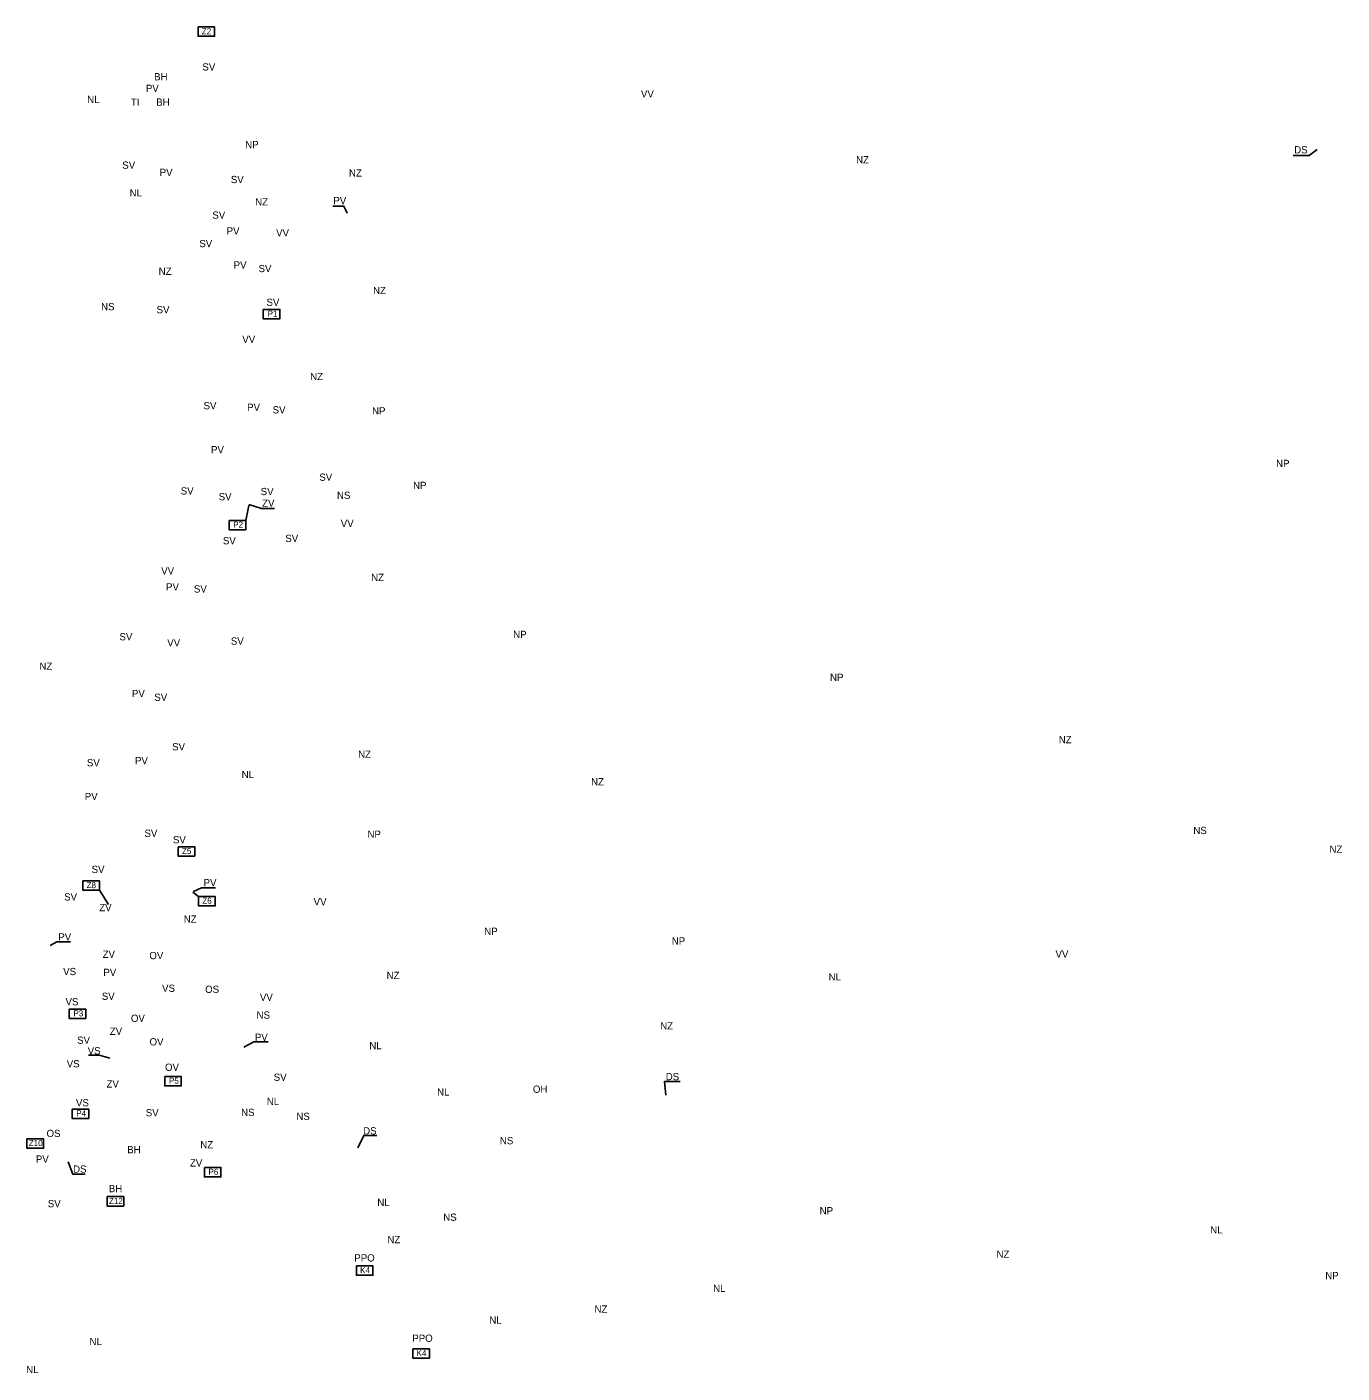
# Model space of a CAD drawing. Extents: x -546576 to -528254, y -1046225 to -1035772.
# Drawn here: x -542762 to -540580, y -1040285 to -1038051 of the extents above; entities that cross this region are included whole.
import ezdxf

# ---------------------------------------------------------------- set-up
doc = ezdxf.new("R2010")
doc.units = 0
for name, color, linetype in [('Vrstva 10', 7, 'Continuous'), ('Vrstva 11', 7, 'Continuous'), ('Vrstva 3', 7, 'Continuous'), ('Vrstva 4', 7, 'Continuous'), ('Vrstva 7', 7, 'Continuous')]:
    doc.layers.add(name, color=color, linetype=linetype)

msp = doc.modelspace()

# ---------------------------------------------------------------- linework, layer by layer
at = {"layer": 'Vrstva 10'}
for points in [[(-540661.6, -1038264.7), (-540634.6, -1038264.7), (-540621.3, -1038254.7)], [(-542254.3, -1038348.8), (-542235.9, -1038348.8), (-542230.2, -1038360.2)], [(-542689, -1039569), (-542711.8, -1039569), (-542722.9, -1039575.2)], [(-542361.3, -1039735), (-542385.1, -1039735), (-542401.8, -1039744)], [(-542659.5, -1039757.3), (-542641.6, -1039757.3), (-542624.1, -1039762.4)], [(-541678, -1039801.2), (-541704.1, -1039801.2), (-541701.7, -1039823.6)], [(-542181.3, -1039890.5), (-542203, -1039890.5), (-542212.9, -1039910.9)], [(-542664.8, -1039954.7), (-542685.3, -1039954.7), (-542693, -1039934.1)]]:
    msp.add_lwpolyline(points, dxfattribs=at)
at = {"layer": 'Vrstva 11'}
for points in [[(-542351.1, -1038850.2), (-542372.4, -1038850.2), (-542393.3, -1038843.9)], [(-542448.9, -1039479.7), (-542472.2, -1039479.7), (-542485.5, -1039485.7)]]:
    msp.add_lwpolyline(points, dxfattribs=at)
at = {"layer": 'Vrstva 3'}
for p, q in [((-542641.3, -1039483.7), (-542626.2, -1039507.2)), ((-542476.8, -1039494.1), (-542486.1, -1039486.6))]:
    msp.add_line(p, q, dxfattribs=at)
for points in [[(-542477.7, -1038051.5), (-542477.7, -1038067), (-542450.2, -1038067), (-542450.2, -1038051.5), (-542477.7, -1038051.5)], [(-542510.8, -1039411.6), (-542510.8, -1039427.1), (-542483.3, -1039427.1), (-542483.3, -1039411.6), (-542510.8, -1039411.6)], [(-542668.8, -1039468.1), (-542668.8, -1039483.7), (-542641.3, -1039483.7), (-542641.3, -1039468.1), (-542668.8, -1039468.1)], [(-542476.8, -1039494.1), (-542476.8, -1039509.6), (-542449.3, -1039509.6), (-542449.3, -1039494.1), (-542476.8, -1039494.1)], [(-542761.5, -1039896.1), (-542761.5, -1039911.6), (-542734, -1039911.6), (-542734, -1039896.1), (-542761.5, -1039896.1)], [(-542628.4, -1039992), (-542628.4, -1040007.5), (-542600.9, -1040007.5), (-542600.9, -1039992), (-542628.4, -1039992)]]:
    msp.add_lwpolyline(points, dxfattribs=at)
at = {"layer": 'Vrstva 4'}
msp.add_line((-542398.7, -1038870.1), (-542393.6, -1038845.3), dxfattribs=at)
for points in [[(-542369.5, -1038520), (-542369.5, -1038535.5), (-542342, -1038535.5), (-542342, -1038520), (-542369.5, -1038520)], [(-542426.2, -1038870.1), (-542426.2, -1038885.6), (-542398.7, -1038885.6), (-542398.7, -1038870.1), (-542426.2, -1038870.1)], [(-542691.4, -1039680.8), (-542691.4, -1039696.3), (-542663.9, -1039696.3), (-542663.9, -1039680.8), (-542691.4, -1039680.8)], [(-542533, -1039792.7), (-542533, -1039808.3), (-542505.5, -1039808.3), (-542505.5, -1039792.7), (-542533, -1039792.7)], [(-542686.5, -1039846.7), (-542686.5, -1039862.2), (-542659, -1039862.2), (-542659, -1039846.7), (-542686.5, -1039846.7)], [(-542467.1, -1039943.6), (-542467.1, -1039959.2), (-542439.7, -1039959.2), (-542439.7, -1039943.6), (-542467.1, -1039943.6)]]:
    msp.add_lwpolyline(points, dxfattribs=at)
at = {"layer": 'Vrstva 7'}
for points in [[(-542215.1, -1040106.9), (-542215.1, -1040122.4), (-542187.6, -1040122.4), (-542187.6, -1040106.9), (-542215.1, -1040106.9)], [(-542121.4, -1040244.3), (-542121.4, -1040259.9), (-542094, -1040259.9), (-542094, -1040244.3), (-542121.4, -1040244.3)]]:
    msp.add_lwpolyline(points, dxfattribs=at)

# ---------------------------------------------------------------- texts
at = {"layer": 'Vrstva 10'}
for s, p in [('BH', (-542550.6, -1038140.1)), ('SV', (-542470.5, -1038123.8)), ('PV', (-542564.2, -1038159.4)), ('NL', (-542661.6, -1038177.7)), ('NL', (-542661.6, -1038177.7)), ('TI', (-542589.1, -1038182.3)), ('BH', (-542547.1, -1038182.2)), ('VV', (-541743.1, -1038168.5)), ('NP', (-542399.5, -1038252.7)), ('DS', (-540659.7, -1038261.3)), ('SV', (-542603.4, -1038286.8)), ('PV', (-542541.4, -1038298.7)), ('NZ', (-541386.3, -1038277.8)), ('SV', (-542423.3, -1038310.6)), ('NZ', (-542227.4, -1038299.8)), ('NL', (-542591.2, -1038332.8)), ('NZ', (-542383, -1038347.7)), ('PV', (-542253.3, -1038345.6)), ('SV', (-542454, -1038369.7)), ('PV', (-542430.3, -1038395.8)), ('VV', (-542348.2, -1038399.1)), ('SV', (-542475.6, -1038416.9)), ('PV', (-542418.7, -1038452.4)), ('NZ', (-542543, -1038462.8)), ('SV', (-542377.4, -1038458.3)), ('NZ', (-542187.4, -1038494.7)), ('NS', (-542638.6, -1038521.5)), ('SV', (-542546.5, -1038526.6)), ('VV', (-542404.3, -1038575.7)), ('NZ', (-542291.8, -1038637.4)), ('SV', (-542468.6, -1038685.8)), ('PV', (-542396.3, -1038688.5)), ('SV', (-542354, -1038692.7)), ('NP', (-542189.1, -1038694.4)), ('PV', (-542456.2, -1038758.8)), ('NP', (-540689.7, -1038781.6)), ('SV', (-542276.6, -1038804.4)), ('SV', (-542506.4, -1038827.2)), ('SV', (-542373.8, -1038828.2)), ('NS', (-542247.3, -1038834.5)), ('NP', (-542121.1, -1038818)), ('SV', (-542443.5, -1038836.8)), ('VV', (-542241, -1038881.1)), ('SV', (-542436.5, -1038909.8)), ('SV', (-542333, -1038906)), ('VV', (-542538.8, -1038959.9)), ('PV', (-542530.8, -1038986.4)), ('SV', (-542484.6, -1038989.8)), ('NZ', (-542190.6, -1038970.7)), ('SV', (-542608, -1039069.1)), ('VV', (-542528.8, -1039079.2)), ('SV', (-542423.3, -1039076.3)), ('NP', (-541955, -1039065.3)), ('NZ', (-542740.8, -1039118)), ('NP', (-541429.5, -1039136.3)), ('PV', (-542587.4, -1039163.3)), ('SV', (-542550.3, -1039169.5)), ('SV', (-542520.7, -1039251.7)), ('NZ', (-541050.1, -1039239.7)), ('SV', (-542662.1, -1039278.1)), ('PV', (-542582.3, -1039274.6)), ('NZ', (-542212.2, -1039263.9)), ('NL', (-542405.3, -1039297.7)), ('NZ', (-541825.8, -1039309.7)), ('PV', (-542665.6, -1039334.1)), ('NS', (-540826.9, -1039390.5)), ('SV', (-542566.6, -1039395.2)), ('NP', (-542196.7, -1039396.7)), ('NZ', (-540601.1, -1039421.6)), ('SV', (-542654.3, -1039455.1)), ('SV', (-542699.8, -1039500.7)), ('VV', (-542286, -1039508.7)), ('NZ', (-542501.4, -1039537.5)), ('PV', (-542709.4, -1039567)), ('NP', (-542003.1, -1039557.8)), ('NP', (-541692, -1039573.8)), ('ZV', (-542636, -1039595.9)), ('OV', (-542558.4, -1039598)), ('VV', (-541055.5, -1039595.6)), ('VS', (-542701.4, -1039624.5)), ('PV', (-542634.8, -1039625.9)), ('NZ', (-542165, -1039630.9)), ('NL', (-541431.9, -1039633.4)), ('VS', (-542537.4, -1039652.2)), ('OS', (-542466, -1039654)), ('SV', (-542637.4, -1039665.5)), ('VV', (-542375.1, -1039667.3)), ('OV', (-542589.1, -1039702.1)), ('NS', (-542380.7, -1039696.7)), ('ZV', (-542624.1, -1039723.6)), ('NZ', (-541711.2, -1039714.6)), ('SV', (-542678.3, -1039738.4)), ('OV', (-542558.2, -1039741.1)), ('PV', (-542383.5, -1039733.5)), ('NL', (-542193.6, -1039747.5)), ('VS', (-542660.7, -1039756)), ('VS', (-542695.5, -1039777.6)), ('ZV', (-542629.5, -1039811)), ('ZV', (-542629.5, -1039811)), ('SV', (-542352.2, -1039799.9)), ('DS', (-541702, -1039798.9)), ('NL', (-542363.7, -1039839.9)), ('NL', (-542081.2, -1039824.3)), ('OH', (-541922.3, -1039819.7)), ('SV', (-542564.4, -1039858.7)), ('NS', (-542406.3, -1039858.2)), ('NS', (-542314.6, -1039864.8)), ('DS', (-542203.9, -1039888.8)), ('NS', (-541977.1, -1039905.1)), ('BH', (-542595.2, -1039920)), ('NZ', (-542474, -1039911.8)), ('PV', (-542746.7, -1039935.7)), ('DS', (-542685, -1039952.2)), ('SV', (-542726.9, -1040009.6)), ('SV', (-542726.9, -1040009.6)), ('NL', (-542180.3, -1040007.6)), ('NS', (-542071, -1040032)), ('NP', (-541446.7, -1040021.3)), ('NL', (-540798.9, -1040053)), ('NZ', (-542163.6, -1040069.2)), ('NZ', (-541153.4, -1040093.4)), ('NP', (-540608.1, -1040128.9)), ('NL', (-541623.4, -1040150)), ('NZ', (-541820.1, -1040184.5)), ('NL', (-541994.5, -1040202.8)), ('NL', (-542657.7, -1040238.3)), ('NL', (-542657.7, -1040238.3)), ('NL', (-542762.8, -1040284.7))]:
    msp.add_text(s, height=12, dxfattribs=at).set_placement(p)
at = {"layer": 'Vrstva 11'}
for s, p in [('SV', (-542364.2, -1038514.3)), ('ZV', (-542371.4, -1038847.5)), ('SV', (-542519.4, -1039405.9)), ('PV', (-542468.5, -1039477.1)), ('ZV', (-542641.6, -1039518.5)), ('VS', (-542697.5, -1039674.6)), ('OV', (-542532.5, -1039783.3)), ('VS', (-542680.1, -1039842.2)), ('OS', (-542729, -1039893.1)), ('ZV', (-542491.2, -1039942.1)), ('BH', (-542625.7, -1039984.6)), ('PPO', (-542218.6, -1040099.6)), ('PPO', (-542122.4, -1040232.8))]:
    msp.add_text(s, height=12, dxfattribs=at).set_placement(p)
at = {"layer": 'Vrstva 3'}
for s, p in [('Z2', (-542471.5, -1038063.6)), ('Z5', (-542504.4, -1039423.7)), ('Z8', (-542662.6, -1039480.2)), ('Z6', (-542470.7, -1039506.1)), ('Z10', (-542758.5, -1039908.1)), ('Z12', (-542625.4, -1040004))]:
    msp.add_text(s, height=10, dxfattribs=at).set_placement(p)
at = {"layer": 'Vrstva 4'}
for s, p in [('P1', (-542362.3, -1038532.1)), ('P2', (-542419.4, -1038882.1)), ('P3', (-542684.4, -1039692.9)), ('P5', (-542526, -1039804.8)), ('P4', (-542679.7, -1039858.7)), ('P6', (-542460.4, -1039955.7))]:
    msp.add_text(s, height=10, dxfattribs=at).set_placement(p)
at = {"layer": 'Vrstva 7'}
for p in [(-542208.9, -1040118.9), (-542115.3, -1040256.4)]:
    msp.add_text('K4', height=10, dxfattribs=at).set_placement(p)

doc.saveas('drawing.dxf')
